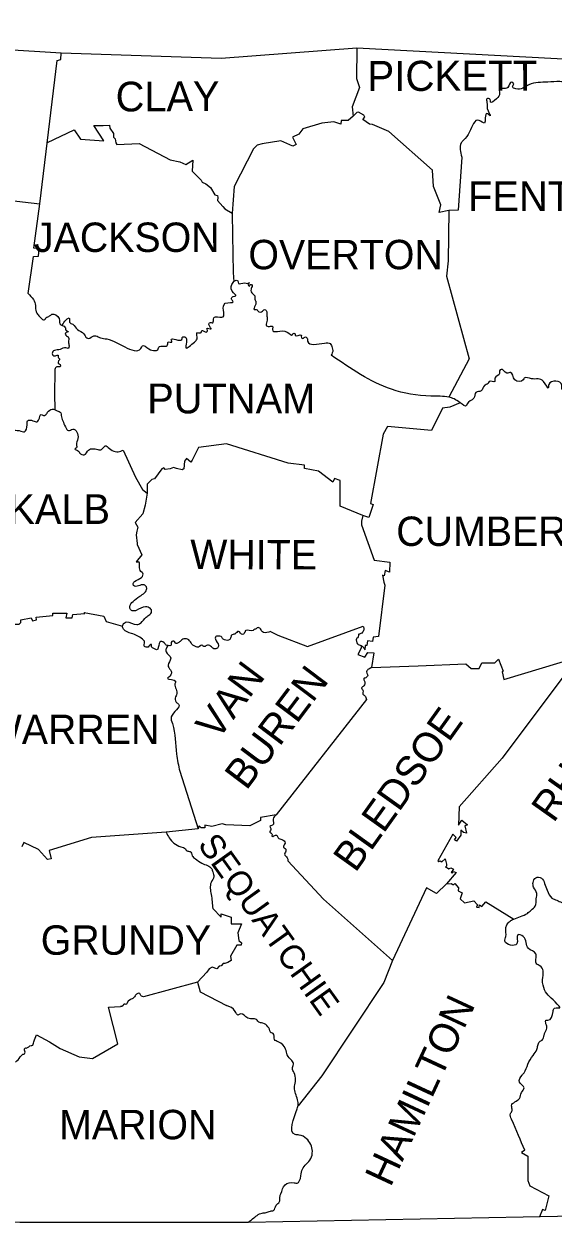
# Model space of a CAD drawing. Extents: x 1623795.1 to 1623879, y 427353.8 to 427391.8.
# Drawn here: x 1623825.667 to 1623826.676, y 427384.016 to 427386.302 of the extents above; entities that cross this region are included whole.
import ezdxf

# ---------------------------------------------------------------- set-up
doc = ezdxf.new("R2010")
doc.units = 0
doc.layers.add('DESIGN - SHEET - Corner Text', color=7, linetype='Continuous')
doc.layers.add('DESIGN - SHEET - Linework', color=7, linetype='Continuous')

msp = doc.modelspace()

# ---------------------------------------------------------------- linework, layer by layer
at = {"layer": 'DESIGN - SHEET - Corner Text'}
for points in [[(1623828.041, 427386.238), (1623827.688, 427386.234), (1623827.41, 427386.228), (1623827.179, 427386.225), (1623826.839, 427386.227), (1623826.302, 427386.256), (1623826.043, 427386.236), (1623825.738, 427386.246), (1623825.502, 427386.261), (1623825.293, 427386.286), (1623825.172, 427386.296), (1623824.974, 427386.301), (1623824.93, 427386.291), (1623824.892, 427386.274), (1623824.861, 427386.302), (1623824.279, 427386.297), (1623823.704, 427386.291)], [(1623825.675, 427385.788), (1623825.685, 427385.858), (1623825.695, 427385.859), (1623825.696, 427385.873), (1623825.686, 427385.874), (1623825.697, 427385.959), (1623825.73, 427386.232), (1623825.737, 427386.234), (1623825.738, 427386.246)], [(1623826.302, 427386.256), (1623826.301, 427386.198), (1623826.307, 427386.181), (1623826.293, 427386.144), (1623826.295, 427386.126)], [(1623826.502, 427386.048), (1623826.495, 427385.947), (1623826.477, 427385.946), (1623826.459, 427385.942), (1623826.462, 427385.957), (1623826.448, 427385.992), (1623826.446, 427386.023), (1623826.363, 427386.097), (1623826.332, 427386.11), (1623826.326, 427386.111), (1623826.313, 427386.12), (1623826.317, 427386.124), (1623826.315, 427386.128), (1623826.305, 427386.134), (1623826.302, 427386.133), (1623826.295, 427386.126), (1623826.285, 427386.118), (1623826.272, 427386.118), (1623826.271, 427386.111), (1623826.258, 427386.115), (1623826.235, 427386.113), (1623826.199, 427386.102), (1623826.191, 427386.092), (1623826.179, 427386.086), (1623826.186, 427386.072), (1623826.18, 427386.069), (1623826.157, 427386.079), (1623826.121, 427386.073), (1623826.112, 427386.071), (1623826.105, 427386.064), (1623826.068, 427385.992), (1623826.064, 427385.941), (1623826.065, 427385.899), (1623826.066, 427385.828), (1623826.067, 427385.81)], [(1623825.712, 427386.076), (1623825.763, 427386.1), (1623825.775, 427386.082), (1623825.819, 427386.079), (1623825.8, 427386.108), (1623825.818, 427386.108), (1623825.83, 427386.109), (1623825.831, 427386.103), (1623825.838, 427386.093), (1623825.838, 427386.086), (1623825.841, 427386.083), (1623825.842, 427386.075), (1623825.844, 427386.072), (1623825.887, 427386.074), (1623825.946, 427386.043), (1623825.964, 427386.039), (1623825.976, 427386.034), (1623825.989, 427386.042), (1623825.988, 427386.021), (1623826.005, 427386.004), (1623826.007, 427386), (1623826.014, 427385.997), (1623826.023, 427385.99), (1623826.031, 427385.976), (1623826.036, 427385.975), (1623826.037, 427385.971), (1623826.036, 427385.965), (1623826.046, 427385.954), (1623826.05, 427385.949), (1623826.064, 427385.941)], [(1623825.202, 427385.875), (1623825.203, 427385.888), (1623825.211, 427385.907), (1623825.213, 427386.028), (1623825.257, 427386.023), (1623825.259, 427386.06), (1623825.247, 427386.065), (1623825.249, 427386.071), (1623825.252, 427386.071), (1623825.256, 427386.071), (1623825.27, 427386.068), (1623825.292, 427386.067), (1623825.324, 427386.003), (1623825.532, 427385.978), (1623825.697, 427385.959)], [(1623826.477, 427385.946), (1623826.476, 427385.85), (1623826.473, 427385.821), (1623826.516, 427385.663), (1623826.477, 427385.59)], [(1623825.726, 427385.639), (1623825.725, 427385.597), (1623825.726, 427385.566)], [(1623826.499, 427385.579), (1623826.479, 427385.571), (1623826.465, 427385.569), (1623826.444, 427385.526), (1623826.36, 427385.534), (1623826.352, 427385.519), (1623826.328, 427385.387), (1623826.333, 427385.385), (1623826.325, 427385.36), (1623826.313, 427385.364), (1623826.27, 427385.382), (1623826.27, 427385.431), (1623826.259, 427385.435), (1623826.256, 427385.428), (1623826.229, 427385.449), (1623826.202, 427385.454), (1623826.202, 427385.46), (1623826.171, 427385.464), (1623826.053, 427385.501), (1623826, 427385.494), (1623825.988, 427385.47), (1623825.985, 427385.466), (1623825.977, 427385.473), (1623825.973, 427385.468), (1623825.972, 427385.453), (1623825.969, 427385.451), (1623825.958, 427385.454), (1623825.952, 427385.456), (1623825.946, 427385.453), (1623825.936, 427385.452), (1623825.934, 427385.455), (1623825.93, 427385.453), (1623825.916, 427385.434), (1623825.911, 427385.433), (1623825.902, 427385.424), (1623825.902, 427385.407), (1623825.898, 427385.384), (1623825.894, 427385.367), (1623825.879, 427385.351), (1623825.884, 427385.342), (1623825.882, 427385.334), (1623825.881, 427385.327), (1623825.883, 427385.311), (1623825.883, 427385.309), (1623825.892, 427385.289), (1623825.881, 427385.276), (1623825.885, 427385.276)], [(1623825.856, 427385.489), (1623825.88, 427385.437), (1623825.893, 427385.414), (1623825.902, 427385.407)], [(1623826.313, 427385.364), (1623826.311, 427385.353), (1623826.311, 427385.346), (1623826.335, 427385.279), (1623826.365, 427385.275), (1623826.364, 427385.256), (1623826.356, 427385.259), (1623826.354, 427385.249), (1623826.351, 427385.25), (1623826.353, 427385.237), (1623826.355, 427385.231), (1623826.343, 427385.133), (1623826.333, 427385.132), (1623826.332, 427385.124), (1623826.322, 427385.125), (1623826.321, 427385.116), (1623826.318, 427385.116), (1623826.317, 427385.108)], [(1623825.65, 427385.157), (1623825.658, 427385.157), (1623825.661, 427385.16), (1623825.661, 427385.165), (1623825.681, 427385.169), (1623825.683, 427385.163), (1623825.691, 427385.165), (1623825.69, 427385.17), (1623825.722, 427385.173), (1623825.722, 427385.178), (1623825.749, 427385.178), (1623825.747, 427385.169), (1623825.759, 427385.169), (1623825.76, 427385.175), (1623825.783, 427385.177), (1623825.782, 427385.179), (1623825.819, 427385.172), (1623825.824, 427385.162), (1623825.855, 427385.153)], [(1623826.137, 427385.143), (1623826.151, 427385.136), (1623826.208, 427385.114), (1623826.314, 427385.153)], [(1623826.31, 427385.115), (1623826.31, 427385.111), (1623826.304, 427385.099), (1623826.317, 427385.094), (1623826.323, 427385.103), (1623826.334, 427385.102), (1623826.33, 427385.074), (1623826.419, 427385.077), (1623826.51, 427385.081), (1623826.52, 427385.072), (1623826.535, 427385.072), (1623826.54, 427385.083), (1623826.565, 427385.083), (1623826.572, 427385.09), (1623826.581, 427385.067), (1623826.579, 427385.066), (1623826.582, 427385.051), (1623826.723, 427385.094), (1623826.744, 427385.1), (1623826.839, 427385.162), (1623826.843, 427385.164), (1623826.861, 427385.164)], [(1623826.723, 427385.094), (1623826.579, 427384.901), (1623826.497, 427384.808), (1623826.496, 427384.773), (1623826.502, 427384.783), (1623826.513, 427384.774), (1623826.508, 427384.772), (1623826.511, 427384.758), (1623826.505, 427384.759), (1623826.5, 427384.764), (1623826.5, 427384.754), (1623826.492, 427384.743), (1623826.488, 427384.745), (1623826.491, 427384.75), (1623826.485, 427384.756), (1623826.456, 427384.705), (1623826.458, 427384.704), (1623826.461, 427384.705), (1623826.464, 427384.703), (1623826.47, 427384.709), (1623826.47, 427384.709), (1623826.473, 427384.699), (1623826.473, 427384.695), (1623826.471, 427384.693), (1623826.475, 427384.692), (1623826.477, 427384.69), (1623826.481, 427384.692), (1623826.486, 427384.689), (1623826.482, 427384.683), (1623826.484, 427384.682), (1623826.486, 427384.685), (1623826.491, 427384.683), (1623826.473, 427384.661), (1623826.454, 427384.643), (1623826.435, 427384.654), (1623826.37, 427384.515), (1623826.353, 427384.473), (1623826.235, 427384.295), (1623826.19, 427384.238)], [(1623826.32, 427385.013), (1623826.148, 427384.793)], [(1623825.964, 427384.876), (1623825.999, 427384.766)], [(1623826.148, 427384.793), (1623826.118, 427384.788), (1623826.118, 427384.782), (1623826.098, 427384.772), (1623826.052, 427384.774), (1623826.045, 427384.776), (1623826.025, 427384.771), (1623826.012, 427384.773), (1623826.012, 427384.768), (1623826.005, 427384.768), (1623826.001, 427384.772), (1623825.999, 427384.766), (1623825.938, 427384.76), (1623825.796, 427384.75), (1623825.715, 427384.725), (1623825.719, 427384.709), (1623825.712, 427384.708), (1623825.695, 427384.727), (1623825.667, 427384.74), (1623825.663, 427384.732)], [(1623826.17, 427384.705), (1623826.238, 427384.632), (1623826.37, 427384.515)], [(1623826.473, 427384.661), (1623826.482, 427384.662), (1623826.485, 427384.66), (1623826.487, 427384.66), (1623826.489, 427384.662), (1623826.496, 427384.654), (1623826.495, 427384.648), (1623826.503, 427384.644), (1623826.499, 427384.633), (1623826.507, 427384.625), (1623826.525, 427384.629), (1623826.532, 427384.621), (1623826.53, 427384.617), (1623826.535, 427384.616), (1623826.536, 427384.621), (1623826.54, 427384.618), (1623826.548, 427384.627), (1623826.601, 427384.594)], [(1623826.027, 427384.614), (1623826.043, 427384.598), (1623826.043, 427384.604), (1623826.062, 427384.598), (1623826.062, 427384.585), (1623826.082, 427384.585), (1623826.075, 427384.568), (1623826.077, 427384.553), (1623826.082, 427384.549), (1623826.081, 427384.544), (1623826.073, 427384.544), (1623826.061, 427384.523), (1623826.062, 427384.515), (1623826.056, 427384.511), (1623826.05, 427384.509), (1623826.047, 427384.509), (1623826.043, 427384.505), (1623826.039, 427384.504), (1623826.035, 427384.499), (1623826.026, 427384.502), (1623826.02, 427384.499), (1623826.016, 427384.493), (1623825.998, 427384.474), (1623825.895, 427384.446)], [(1623825.998, 427384.474), (1623826.003, 427384.455), (1623826.053, 427384.429)], [(1623820.668, 427384.137), (1623821.921, 427384.089), (1623822.838, 427384.065), (1623823.04, 427384.061), (1623823.033, 427384.084), (1623823.705, 427384.062), (1623824.131, 427384.052), (1623824.561, 427384.032), (1623825.145, 427384.022), (1623825.659, 427384.016), (1623826.095, 427384.016), (1623826.881, 427384.031), (1623827.392, 427384.041), (1623827.421, 427384.371), (1623827.486, 427384.417)], [(1623825.691, 427384.373), (1623825.716, 427384.36), (1623825.736, 427384.347), (1623825.772, 427384.331), (1623825.798, 427384.328), (1623825.846, 427384.356), (1623825.828, 427384.426), (1623825.851, 427384.427)], [(1623826.622, 427384.153), (1623826.616, 427384.149), (1623826.628, 427384.142), (1623826.628, 427384.095), (1623826.632, 427384.085), (1623826.668, 427384.066), (1623826.661, 427384.038), (1623826.656, 427384.04), (1623826.65, 427384.026)]]:
    msp.add_lwpolyline(points, dxfattribs=at)
for points in [[(1623826.84, 427386.121), (1623826.833, 427386.128), (1623826.817, 427386.142), (1623826.797, 427386.157), (1623826.774, 427386.168), (1623826.747, 427386.181), (1623826.715, 427386.188), (1623826.689, 427386.192), (1623826.666, 427386.191), (1623826.63, 427386.186), (1623826.605, 427386.178), (1623826.599, 427386.182), (1623826.601, 427386.188), (1623826.597, 427386.191), (1623826.59, 427386.181), (1623826.579, 427386.179), (1623826.574, 427386.179), (1623826.574, 427386.17), (1623826.568, 427386.159), (1623826.557, 427386.153), (1623826.556, 427386.158), (1623826.55, 427386.159), (1623826.55, 427386.153), (1623826.552, 427386.136), (1623826.556, 427386.127), (1623826.55, 427386.131), (1623826.545, 427386.113), (1623826.535, 427386.118), (1623826.517, 427386.096), (1623826.505, 427386.08), (1623826.501, 427386.075), (1623826.502, 427386.048)], [(1623825.917, 427385.679), (1623825.922, 427385.68), (1623825.924, 427385.685), (1623825.941, 427385.69), (1623825.942, 427385.695), (1623825.949, 427385.695), (1623825.948, 427385.699), (1623825.968, 427385.7), (1623825.969, 427385.704), (1623825.974, 427385.705), (1623825.976, 427385.684), (1623825.992, 427385.695), (1623825.997, 427385.701), (1623825.998, 427385.713), (1623826.005, 427385.713), (1623826.006, 427385.717), (1623826.015, 427385.714), (1623826.017, 427385.717), (1623826.016, 427385.721), (1623826.024, 427385.72), (1623826.02, 427385.727), (1623826.021, 427385.732), (1623826.027, 427385.732), (1623826.029, 427385.741), (1623826.032, 427385.743), (1623826.047, 427385.743), (1623826.051, 427385.769), (1623826.066, 427385.772), (1623826.063, 427385.777), (1623826.066, 427385.782), (1623826.071, 427385.783), (1623826.064, 427385.792), (1623826.066, 427385.809), (1623826.072, 427385.813), (1623826.075, 427385.812), (1623826.076, 427385.807), (1623826.088, 427385.808), (1623826.093, 427385.807), (1623826.097, 427385.809), (1623826.095, 427385.803), (1623826.097, 427385.802), (1623826.099, 427385.805), (1623826.102, 427385.803), (1623826.101, 427385.799), (1623826.1, 427385.796), (1623826.1, 427385.791), (1623826.107, 427385.783), (1623826.108, 427385.775), (1623826.109, 427385.773), (1623826.108, 427385.765), (1623826.106, 427385.757), (1623826.11, 427385.757), (1623826.115, 427385.753), (1623826.12, 427385.753), (1623826.126, 427385.757), (1623826.129, 427385.755), (1623826.13, 427385.746), (1623826.131, 427385.739), (1623826.129, 427385.729), (1623826.129, 427385.727), (1623826.135, 427385.725), (1623826.141, 427385.725), (1623826.141, 427385.719), (1623826.169, 427385.714), (1623826.179, 427385.709), (1623826.18, 427385.711), (1623826.184, 427385.711), (1623826.184, 427385.708), (1623826.196, 427385.708), (1623826.196, 427385.704), (1623826.199, 427385.702), (1623826.204, 427385.705), (1623826.206, 427385.704), (1623826.208, 427385.697), (1623826.24, 427385.693), (1623826.251, 427385.692), (1623826.255, 427385.684), (1623826.256, 427385.679), (1623826.253, 427385.67)], [(1623825.675, 427385.788), (1623825.685, 427385.776), (1623825.689, 427385.765), (1623825.69, 427385.753), (1623825.694, 427385.747), (1623825.707, 427385.738), (1623825.709, 427385.741), (1623825.716, 427385.745), (1623825.72, 427385.748), (1623825.734, 427385.74), (1623825.737, 427385.728), (1623825.74, 427385.727), (1623825.746, 427385.722), (1623825.747, 427385.718), (1623825.752, 427385.715), (1623825.746, 427385.712), (1623825.747, 427385.708), (1623825.752, 427385.704), (1623825.752, 427385.695), (1623825.753, 427385.688), (1623825.751, 427385.683), (1623825.747, 427385.684), (1623825.736, 427385.681), (1623825.725, 427385.679), (1623825.722, 427385.677), (1623825.722, 427385.67), (1623825.727, 427385.669), (1623825.732, 427385.67), (1623825.733, 427385.665), (1623825.735, 427385.663), (1623825.733, 427385.659), (1623825.732, 427385.655), (1623825.736, 427385.652), (1623825.736, 427385.648), (1623825.733, 427385.648), (1623825.727, 427385.646), (1623825.726, 427385.639)], [(1623825.74, 427385.727), (1623825.748, 427385.738), (1623825.753, 427385.741), (1623825.754, 427385.733), (1623825.76, 427385.729), (1623825.769, 427385.719), (1623825.781, 427385.711), (1623825.787, 427385.703), (1623825.79, 427385.702), (1623825.8, 427385.707), (1623825.804, 427385.707), (1623825.813, 427385.703), (1623825.825, 427385.701), (1623825.892, 427385.686), (1623825.893, 427385.688), (1623825.905, 427385.682), (1623825.917, 427385.679)], [(1623826.72, 427385.624), (1623826.713, 427385.62), (1623826.708, 427385.618), (1623826.7, 427385.606), (1623826.693, 427385.605), (1623826.693, 427385.613), (1623826.668, 427385.614), (1623826.667, 427385.607), (1623826.658, 427385.62), (1623826.635, 427385.625), (1623826.621, 427385.626), (1623826.619, 427385.623), (1623826.603, 427385.623), (1623826.595, 427385.637), (1623826.588, 427385.636), (1623826.577, 427385.643), (1623826.574, 427385.64), (1623826.574, 427385.635), (1623826.565, 427385.626), (1623826.565, 427385.62), (1623826.554, 427385.62), (1623826.552, 427385.616), (1623826.545, 427385.612), (1623826.539, 427385.602), (1623826.529, 427385.599), (1623826.525, 427385.588), (1623826.512, 427385.577), (1623826.511, 427385.574), (1623826.499, 427385.579), (1623826.477, 427385.59), (1623826.443, 427385.592), (1623826.368, 427385.605), (1623826.253, 427385.67)], [(1623825.454, 427385.517), (1623825.457, 427385.52), (1623825.462, 427385.52), (1623825.474, 427385.512), (1623825.484, 427385.512), (1623825.491, 427385.512), (1623825.498, 427385.512), (1623825.506, 427385.51), (1623825.512, 427385.517), (1623825.518, 427385.509), (1623825.522, 427385.509), (1623825.528, 427385.517), (1623825.533, 427385.513), (1623825.549, 427385.523), (1623825.567, 427385.539), (1623825.572, 427385.539), (1623825.578, 427385.533), (1623825.589, 427385.533), (1623825.594, 427385.54), (1623825.6, 427385.539), (1623825.602, 427385.531), (1623825.614, 427385.532), (1623825.626, 427385.552), (1623825.634, 427385.548), (1623825.64, 427385.547), (1623825.639, 427385.54), (1623825.644, 427385.535), (1623825.645, 427385.53), (1623825.658, 427385.526), (1623825.668, 427385.524), (1623825.673, 427385.537), (1623825.674, 427385.545), (1623825.684, 427385.545), (1623825.692, 427385.543), (1623825.695, 427385.546), (1623825.7, 427385.557), (1623825.704, 427385.555), (1623825.708, 427385.556), (1623825.712, 427385.561), (1623825.721, 427385.567), (1623825.73, 427385.564), (1623825.737, 427385.56), (1623825.738, 427385.555), (1623825.741, 427385.545), (1623825.746, 427385.533), (1623825.752, 427385.526), (1623825.76, 427385.529), (1623825.77, 427385.511), (1623825.767, 427385.499), (1623825.767, 427385.493), (1623825.764, 427385.491), (1623825.771, 427385.487), (1623825.773, 427385.484), (1623825.782, 427385.48), (1623825.79, 427385.489), (1623825.808, 427385.49), (1623825.815, 427385.49), (1623825.822, 427385.497), (1623825.83, 427385.492), (1623825.852, 427385.487), (1623825.856, 427385.489)], [(1623826.137, 427385.143), (1623826.124, 427385.141), (1623826.12, 427385.144), (1623826.118, 427385.148), (1623826.112, 427385.15), (1623826.11, 427385.148), (1623826.105, 427385.146), (1623826.104, 427385.145), (1623826.09, 427385.145), (1623826.087, 427385.139), (1623826.084, 427385.137), (1623826.076, 427385.143), (1623826.069, 427385.138), (1623826.063, 427385.136), (1623826.061, 427385.13), (1623826.057, 427385.126), (1623826.052, 427385.126), (1623826.047, 427385.128), (1623826.043, 427385.133), (1623826.038, 427385.134), (1623826.032, 427385.132), (1623826.032, 427385.128), (1623826.038, 427385.116), (1623826.036, 427385.111), (1623826.029, 427385.11), (1623826.023, 427385.115), (1623826.015, 427385.116), (1623826.01, 427385.114), (1623826.008, 427385.116), (1623826.004, 427385.116), (1623826, 427385.113), (1623825.994, 427385.114), (1623825.989, 427385.117), (1623825.983, 427385.125), (1623825.979, 427385.128), (1623825.97, 427385.128), (1623825.966, 427385.125), (1623825.961, 427385.121), (1623825.956, 427385.12), (1623825.954, 427385.124), (1623825.948, 427385.122), (1623825.947, 427385.116), (1623825.942, 427385.116), (1623825.938, 427385.117), (1623825.936, 427385.119), (1623825.928, 427385.124), (1623825.925, 427385.12), (1623825.92, 427385.108), (1623825.917, 427385.109), (1623825.91, 427385.116), (1623825.91, 427385.118), (1623825.907, 427385.117), (1623825.904, 427385.113), (1623825.9, 427385.113), (1623825.897, 427385.114), (1623825.896, 427385.118), (1623825.897, 427385.123), (1623825.893, 427385.128), (1623825.872, 427385.139), (1623825.857, 427385.147), (1623825.855, 427385.153), (1623825.858, 427385.159), (1623825.862, 427385.161), (1623825.882, 427385.156), (1623825.89, 427385.159), (1623825.9, 427385.17), (1623825.907, 427385.175), (1623825.91, 427385.179), (1623825.91, 427385.184), (1623825.904, 427385.189), (1623825.899, 427385.19), (1623825.881, 427385.183), (1623825.875, 427385.182), (1623825.87, 427385.185), (1623825.869, 427385.19), (1623825.875, 427385.2), (1623825.888, 427385.21), (1623825.901, 427385.225), (1623825.899, 427385.23), (1623825.893, 427385.232), (1623825.883, 427385.229), (1623825.878, 427385.229), (1623825.875, 427385.233), (1623825.878, 427385.238), (1623825.891, 427385.246), (1623825.894, 427385.25), (1623825.894, 427385.254), (1623825.89, 427385.257), (1623825.885, 427385.276), (1623825.881, 427385.276)], [(1623826.314, 427385.153), (1623826.315, 427385.146), (1623826.314, 427385.143), (1623826.307, 427385.138), (1623826.305, 427385.137), (1623826.305, 427385.135), (1623826.303, 427385.131), (1623826.301, 427385.129), (1623826.301, 427385.124), (1623826.303, 427385.119), (1623826.31, 427385.116), (1623826.317, 427385.108)], [(1623825.942, 427385.116), (1623825.938, 427385.11), (1623825.938, 427385.104), (1623825.947, 427385.092), (1623825.946, 427385.088), (1623825.942, 427385.076), (1623825.948, 427385.067), (1623825.947, 427385.06), (1623825.941, 427385.053), (1623825.956, 427385.048), (1623825.955, 427385.043), (1623825.957, 427385.033), (1623825.958, 427385.022), (1623825.956, 427385.018), (1623825.957, 427385.008), (1623825.962, 427385.004), (1623825.948, 427384.98), (1623825.95, 427384.967), (1623825.958, 427384.909), (1623825.964, 427384.876)], [(1623826.33, 427385.074), (1623826.323, 427385.07), (1623826.321, 427385.068), (1623826.321, 427385.063), (1623826.323, 427385.059), (1623826.321, 427385.056), (1623826.317, 427385.054), (1623826.316, 427385.054), (1623826.315, 427385.052), (1623826.317, 427385.047), (1623826.317, 427385.043), (1623826.315, 427385.039), (1623826.311, 427385.035), (1623826.314, 427385.029), (1623826.313, 427385.024), (1623826.317, 427385.02), (1623826.32, 427385.013)], [(1623826.622, 427384.153), (1623826.597, 427384.212), (1623826.595, 427384.223), (1623826.598, 427384.229), (1623826.597, 427384.238), (1623826.612, 427384.252), (1623826.616, 427384.263), (1623826.621, 427384.272), (1623826.612, 427384.283), (1623826.617, 427384.296), (1623826.621, 427384.301), (1623826.628, 427384.317), (1623826.638, 427384.334), (1623826.645, 427384.345), (1623826.647, 427384.353), (1623826.65, 427384.36), (1623826.655, 427384.363), (1623826.659, 427384.373), (1623826.66, 427384.376), (1623826.664, 427384.386), (1623826.664, 427384.39), (1623826.662, 427384.396), (1623826.662, 427384.401), (1623826.666, 427384.401), (1623826.676, 427384.418), (1623826.679, 427384.424), (1623826.689, 427384.425), (1623826.684, 427384.432), (1623826.66, 427384.459), (1623826.656, 427384.478), (1623826.657, 427384.495), (1623826.651, 427384.505), (1623826.645, 427384.508), (1623826.643, 427384.528), (1623826.629, 427384.538), (1623826.619, 427384.561), (1623826.609, 427384.564), (1623826.607, 427384.547), (1623826.584, 427384.552), (1623826.586, 427384.561), (1623826.586, 427384.576), (1623826.588, 427384.583), (1623826.594, 427384.59), (1623826.597, 427384.592), (1623826.601, 427384.594), (1623826.614, 427384.599), (1623826.627, 427384.605), (1623826.634, 427384.611), (1623826.642, 427384.619), (1623826.644, 427384.633), (1623826.645, 427384.643), (1623826.639, 427384.655), (1623826.638, 427384.664), (1623826.643, 427384.673), (1623826.654, 427384.672), (1623826.66, 427384.662), (1623826.665, 427384.649), (1623826.674, 427384.634), (1623826.683, 427384.63), (1623826.693, 427384.626), (1623826.715, 427384.628), (1623826.727, 427384.64), (1623826.731, 427384.652), (1623826.727, 427384.669), (1623826.729, 427384.683), (1623826.734, 427384.688), (1623826.757, 427384.692), (1623826.769, 427384.696), (1623826.774, 427384.703), (1623826.779, 427384.714), (1623826.773, 427384.731), (1623826.761, 427384.74), (1623826.756, 427384.753), (1623826.753, 427384.759), (1623826.756, 427384.77), (1623826.765, 427384.78), (1623826.777, 427384.784), (1623826.791, 427384.784), (1623826.807, 427384.78), (1623826.827, 427384.778), (1623826.842, 427384.779), (1623826.849, 427384.793), (1623826.842, 427384.801), (1623826.832, 427384.805), (1623826.826, 427384.813), (1623826.828, 427384.821), (1623826.836, 427384.838), (1623826.845, 427384.842), (1623826.864, 427384.848), (1623826.865, 427384.864), (1623826.853, 427384.888)], [(1623826.148, 427384.793), (1623826.142, 427384.785), (1623826.141, 427384.773), (1623826.136, 427384.771), (1623826.138, 427384.767), (1623826.136, 427384.76), (1623826.14, 427384.757), (1623826.14, 427384.752), (1623826.149, 427384.754), (1623826.152, 427384.749), (1623826.159, 427384.746), (1623826.165, 427384.739), (1623826.162, 427384.731), (1623826.165, 427384.729), (1623826.166, 427384.722), (1623826.164, 427384.718), (1623826.169, 427384.711), (1623826.17, 427384.705)], [(1623825.938, 427384.76), (1623825.944, 427384.749), (1623825.953, 427384.739), (1623825.966, 427384.732), (1623825.975, 427384.728), (1623825.978, 427384.724), (1623825.984, 427384.723), (1623825.988, 427384.715), (1623825.994, 427384.709), (1623826.006, 427384.701), (1623826.017, 427384.696), (1623826.025, 427384.69), (1623826.027, 427384.684), (1623826.029, 427384.675), (1623826.024, 427384.664), (1623826.024, 427384.641), (1623826.027, 427384.614)], [(1623825.895, 427384.446), (1623825.891, 427384.447), (1623825.888, 427384.452), (1623825.884, 427384.452), (1623825.88, 427384.449), (1623825.878, 427384.446), (1623825.863, 427384.433), (1623825.862, 427384.431), (1623825.858, 427384.432), (1623825.856, 427384.429), (1623825.851, 427384.427)], [(1623826.095, 427384.016), (1623826.103, 427384.022), (1623826.121, 427384.033), (1623826.129, 427384.034), (1623826.137, 427384.037), (1623826.143, 427384.038), (1623826.148, 427384.048), (1623826.154, 427384.054), (1623826.155, 427384.064), (1623826.157, 427384.07), (1623826.165, 427384.087), (1623826.182, 427384.091), (1623826.188, 427384.09), (1623826.195, 427384.104), (1623826.198, 427384.117), (1623826.214, 427384.137), (1623826.217, 427384.151), (1623826.206, 427384.175), (1623826.192, 427384.182), (1623826.184, 427384.183), (1623826.188, 427384.232), (1623826.19, 427384.241), (1623826.184, 427384.264), (1623826.183, 427384.275), (1623826.185, 427384.287), (1623826.182, 427384.301), (1623826.179, 427384.309), (1623826.181, 427384.317), (1623826.178, 427384.324), (1623826.169, 427384.335), (1623826.166, 427384.346), (1623826.152, 427384.36), (1623826.145, 427384.364), (1623826.142, 427384.376), (1623826.137, 427384.378), (1623826.136, 427384.381), (1623826.12, 427384.396), (1623826.114, 427384.398), (1623826.112, 427384.401), (1623826.094, 427384.405), (1623826.08, 427384.413), (1623826.075, 427384.411), (1623826.07, 427384.418), (1623826.053, 427384.429)], [(1623825.651, 427384.321), (1623825.66, 427384.331), (1623825.665, 427384.336), (1623825.668, 427384.337), (1623825.669, 427384.34), (1623825.668, 427384.344), (1623825.669, 427384.348), (1623825.671, 427384.348), (1623825.681, 427384.353), (1623825.682, 427384.353), (1623825.686, 427384.36), (1623825.691, 427384.373)]]:
    msp.add_spline(points, degree=3, dxfattribs=at)

# ---------------------------------------------------------------- texts
at = {"layer": 'DESIGN - SHEET - Linework'}
for s, height, rotation, p in [('PICKETT', 0.05741, 0.1429, (1623826.322, 427386.174)), ('CLAY', 0.05668, 0.2558, (1623825.842, 427386.135)), ('WHITE', 0.05608, 359.7968, (1623825.984, 427385.262)), ('VAN', 0.05647, 53.1301, (1623826.036, 427384.933)), ('BUREN', 0.05647, 52.9269, (1623826.091, 427384.838)), ('BLEDSOE', 0.05639, 54.3955, (1623826.299, 427384.681)), ('RHEA', 0.05639, 54.6107, (1623826.677, 427384.776)), ('SEQUATCHIE', 0.04667, 305.6229, (1623825.997, 427384.736)), ('HAMILTON', 0.05585, 65.0587, (1623826.366, 427384.081))]:
    msp.add_text(s, height=height, rotation=rotation, dxfattribs=at).set_placement(p)
for s, height, p in [('FENTRESS', 0.05681, (1623826.514, 427385.945)), ('JACKSON', 0.05608, (1623825.686, 427385.867)), ('OVERTON', 0.05608, (1623826.095, 427385.834)), ('PUTNAM', 0.05681, (1623825.902, 427385.559)), ('DEKALB', 0.05668, (1623825.532, 427385.348)), ('CUMBERLAND', 0.05608, (1623826.377, 427385.306)), ('WARREN', 0.05608, (1623825.592, 427384.928)), ('GRUNDY', 0.05608, (1623825.699, 427384.526)), ('MARION', 0.05608, (1623825.734, 427384.174))]:
    msp.add_text(s, height=height, dxfattribs=at).set_placement(p)

doc.saveas('drawing.dxf')
